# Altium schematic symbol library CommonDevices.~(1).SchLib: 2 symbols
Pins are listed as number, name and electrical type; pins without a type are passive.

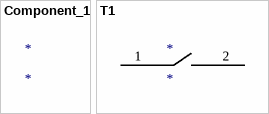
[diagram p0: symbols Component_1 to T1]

## Component_1
designator *

## T1
designator *
pins: 1, 2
